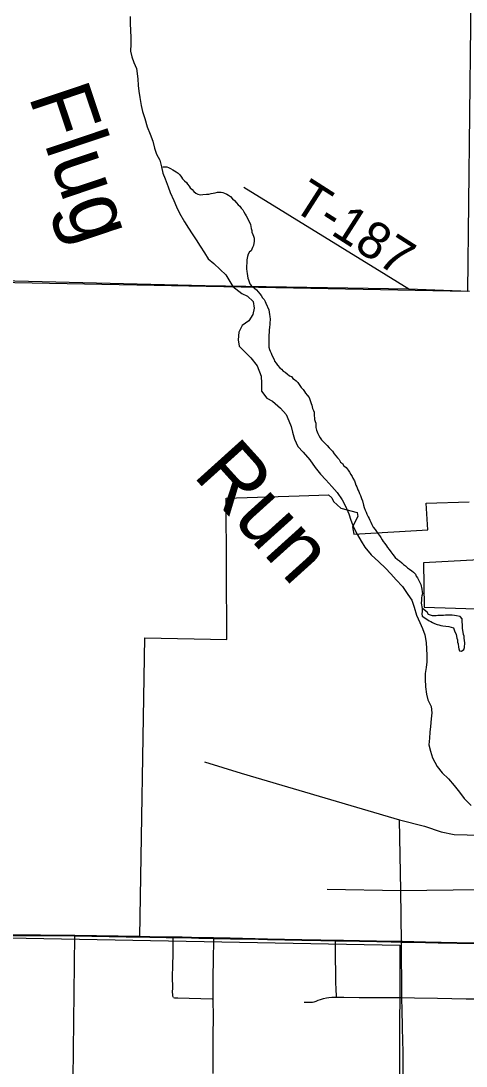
# Model space of a CAD drawing. Extents: x -8.5 to 18.7, y -20.3 to 7.
# Drawn here: x 0.015 to 1.387, y -11.043 to -7.821 of the extents above; entities that cross this region are included whole.
import ezdxf

# ---------------------------------------------------------------- set-up
doc = ezdxf.new("R2010")
doc.units = 0
for name, color, linetype in [('GM_X_City_Street', 7, 'Continuous'), ('GM_X_Corporation', 7, 'Continuous'), ('GM_X_County_Road', 7, 'Continuous'), ('GM_X_Minor_Lake', 7, 'Continuous'), ('GM_X_Minor_River', 7, 'Continuous'), ('GM_X_Minor_River_Text', 7, 'Continuous'), ('GM_X_Section', 7, 'Continuous'), ('GM_X_Township', 7, 'Continuous'), ('GM_X_Township_Road', 7, 'Continuous'), ('GM_X_Township_Road_Text', 7, 'Continuous'), ('SH_Cut_Line', 7, 'Continuous')]:
    doc.layers.add(name, color=color, linetype=linetype)

msp = doc.modelspace()

# ---------------------------------------------------------------- linework, layer by layer
at = {"layer": 'GM_X_City_Street'}
msp.add_line((0.5807, -10.1045), (0.6942, -10.1394), dxfattribs=at)
for points in [[(0.6942, -10.1394), (0.7397, -10.1534), (1.1822, -10.284)], [(1.1822, -10.284), (1.2591, -10.3029), (1.3106, -10.3202), (1.3502, -10.3292), (1.4311, -10.3306)], [(1.1888, -10.6602), (1.1863, -10.501), (1.1822, -10.284)], [(0.9593, -10.4974), (1.1863, -10.501), (1.4281, -10.4988), (1.6026, -10.5019), (1.737, -10.5007)], [(0.4857, -10.8311), (0.4845, -10.8292), (0.4839, -10.8272), (0.4834, -10.8248), (0.4833, -10.8223), (0.4829, -10.8148), (0.4831, -10.8017), (0.4829, -10.7673), (0.4836, -10.7322), (0.4844, -10.6971), (0.4846, -10.6749), (0.4848, -10.6495), (0.4848, -10.6466)], [(0.6078, -11.0651), (0.6078, -11.061), (0.6079, -11.0447), (0.6078, -10.9475), (0.6084, -10.8928), (0.6082, -10.8351), (0.6081, -10.8218), (0.608, -10.767), (0.6084, -10.716), (0.6094, -10.652), (0.6094, -10.6489)], [(0.9884, -10.8303), (0.9878, -10.823), (0.9869, -10.8094), (0.9857, -10.7809), (0.9855, -10.749), (0.9853, -10.7154), (0.9852, -10.6854), (0.985, -10.6603), (0.9849, -10.6564)], [(1.1941, -11.6193), (1.1917, -11.6053), (1.1907, -11.5951), (1.1892, -11.5686), (1.1895, -11.5362), (1.1907, -11.4767), (1.1907, -11.4495), (1.1914, -11.3481), (1.1913, -11.2804), (1.1931, -11.1293), (1.1934, -11.089), (1.1935, -11.0702), (1.1936, -11.0591), (1.1937, -11.0477), (1.1938, -11.0281), (1.1933, -10.9999), (1.1919, -10.9262), (1.19, -10.865), (1.1896, -10.8383), (1.1895, -10.8317), (1.1889, -10.7867), (1.1888, -10.7005), (1.1888, -10.664), (1.1888, -10.6602)], [(0.4857, -10.8311), (0.4885, -10.8321), (0.4911, -10.8325), (0.4947, -10.8326), (0.4989, -10.8325), (0.6042, -10.835), (0.6082, -10.8351)], [(0.8886, -10.8456), (0.906, -10.8459), (0.9137, -10.8452), (0.919, -10.8444), (0.9248, -10.8426), (0.9319, -10.84), (0.9388, -10.8371), (0.9481, -10.8344), (0.957, -10.8326), (0.9641, -10.8315), (0.9738, -10.8307), (0.9834, -10.8304), (0.9884, -10.8303), (1.0107, -10.83), (1.0579, -10.831), (1.0965, -10.8312), (1.1574, -10.8316), (1.1895, -10.8317), (1.2281, -10.8319), (1.299, -10.8334), (1.3878, -10.8352), (1.4261, -10.8355)]]:
    msp.add_lwpolyline(points, dxfattribs=at)
at = {"layer": 'GM_X_Corporation'}
for points in [[(0.1698, -11.612), (0.181, -10.6399), (0.3813, -10.6434), (0.3973, -9.7225), (0.6499, -9.7277), (0.6475, -9.2921), (0.8727, -9.2849), (0.9632, -9.2821), (0.9736, -9.2911), (0.9792, -9.3026), (1.0013, -9.3223), (1.0518, -9.3363), (1.0538, -9.348), (1.0371, -9.3806), (1.0419, -9.4031), (1.2694, -9.3892), (1.2642, -9.3076), (1.3973, -9.3029)], [(1.4272, -9.4823), (1.2561, -9.4913), (1.2586, -9.6281), (1.4512, -9.6345)], [(1.4265, -10.6639), (1.3594, -10.6624), (1.262, -10.6605), (1.1917, -10.6591), (1.1883, -10.6591), (1.1558, -10.6587), (1.1114, -10.6578), (1.0587, -10.6567), (1.01, -10.6558), (0.9885, -10.6554), (0.9845, -10.6553), (0.9393, -10.6545), (0.8811, -10.6531), (0.7751, -10.6511), (0.6606, -10.6488), (0.609, -10.6478), (0.5997, -10.6475), (0.5626, -10.647), (0.5409, -10.6464), (0.5118, -10.6457), (0.4843, -10.6455), (0.4621, -10.6453), (0.4123, -10.644), (0.3813, -10.6434), (0.181, -10.6399), (0.0755, -10.6395), (-0.1044, -10.6386)]]:
    msp.add_lwpolyline(points, dxfattribs=at)
at = {"layer": 'GM_X_County_Road'}
for p, q in [((0.1814, -10.641), (0.3397, -10.6438)), ((0.3397, -10.6438), (0.3817, -10.6445)), ((1.3776, -10.6639), (1.4269, -10.665))]:
    msp.add_line(p, q, dxfattribs=at)
for points in [[(-0.6374, -8.6114), (-0.6211, -8.6091), (-0.5859, -8.6093), (-0.2973, -8.6151), (0.5826, -8.6362), (1.2105, -8.6468), (1.398, -8.6543)], [(-0.729, -10.6299), (-0.6981, -10.6302), (-0.6198, -10.6313), (-0.5055, -10.6329), (-0.4073, -10.6347), (-0.3249, -10.6363), (-0.2072, -10.6385), (-0.104, -10.6397), (0.076, -10.6406), (0.1814, -10.641)], [(0.3817, -10.6445), (0.4127, -10.6451), (0.4626, -10.6464), (0.4848, -10.6466)], [(0.4848, -10.6466), (0.5122, -10.6468), (0.5413, -10.6475), (0.5631, -10.6481), (0.6001, -10.6486), (0.6094, -10.6489)], [(0.6094, -10.6489), (0.6611, -10.6499), (0.7474, -10.6516)], [(0.7474, -10.6516), (0.7756, -10.6522), (0.8816, -10.6542), (0.9398, -10.6556), (0.9849, -10.6564)], [(0.9849, -10.6564), (0.989, -10.6565), (1.0104, -10.6569), (1.0592, -10.6578), (1.1118, -10.6589), (1.1562, -10.6598), (1.1888, -10.6602)], [(1.1888, -10.6602), (1.1922, -10.6602), (1.2624, -10.6616), (1.301, -10.6623)], [(1.301, -10.6623), (1.3598, -10.6635), (1.3776, -10.6639)]]:
    msp.add_lwpolyline(points, dxfattribs=at)
at = {"layer": 'GM_X_Minor_Lake'}
for points in [[(1.2529, -9.6317), (1.2521, -9.6347), (1.2519, -9.6415), (1.251, -9.6483), (1.2524, -9.6552)], [(1.2524, -9.6552), (1.2598, -9.6606), (1.2733, -9.67), (1.2785, -9.6724), (1.2838, -9.6755), (1.2905, -9.6787), (1.298, -9.6811), (1.3033, -9.6827), (1.3101, -9.6844), (1.3161, -9.6853), (1.3252, -9.6862), (1.3342, -9.6879), (1.3418, -9.6896), (1.3486, -9.6912), (1.3507, -9.6974), (1.3528, -9.7042), (1.3572, -9.7111), (1.3578, -9.718), (1.3592, -9.7233), (1.3614, -9.7287), (1.3613, -9.7355), (1.3627, -9.7408), (1.364, -9.7515), (1.3654, -9.7568), (1.3675, -9.7622), (1.3735, -9.7638), (1.3805, -9.7587), (1.3829, -9.7519), (1.3832, -9.7375), (1.3826, -9.7306), (1.3812, -9.7238), (1.3813, -9.7177), (1.3799, -9.7124), (1.3772, -9.6986), (1.3765, -9.6933), (1.3766, -9.688), (1.376, -9.6812), (1.3754, -9.6743), (1.3755, -9.669), (1.3749, -9.6637), (1.369, -9.6568), (1.3584, -9.655), (1.3516, -9.6534), (1.3441, -9.6525), (1.3304, -9.6522), (1.3236, -9.6528), (1.3175, -9.6534), (1.3107, -9.6533), (1.3054, -9.654), (1.3001, -9.6539), (1.2948, -9.6545), (1.2835, -9.6543), (1.2774, -9.6526), (1.2714, -9.6502), (1.267, -9.6433), (1.2529, -9.6317)]]:
    msp.add_lwpolyline(points, dxfattribs=at)
at = {"layer": 'GM_X_Minor_River'}
for points in [[(0.3516, -7.8072), (0.3514, -7.8292), (0.3526, -7.849), (0.3539, -7.8733), (0.3537, -7.8923), (0.3527, -7.9135), (0.357, -7.931), (0.3629, -7.9485), (0.3718, -7.9676), (0.3752, -7.9995), (0.3765, -8.0193), (0.3786, -8.0375), (0.3814, -8.0573), (0.3857, -8.0817), (0.39, -8.0999), (0.3966, -8.1212), (0.4046, -8.1472), (0.4135, -8.17), (0.4216, -8.1914), (0.4274, -8.2127), (0.4333, -8.2317), (0.4437, -8.2501), (0.448, -8.2706), (0.4531, -8.2904), (0.4597, -8.3079), (0.4693, -8.3323), (0.4752, -8.3499), (0.487, -8.3743), (0.4951, -8.3941), (0.504, -8.4132), (0.5197, -8.4399), (0.5316, -8.4591), (0.5435, -8.4766), (0.5554, -8.4958), (0.5681, -8.5149), (0.5808, -8.5355), (0.5919, -8.5546), (0.61, -8.5685), (0.6295, -8.5869), (0.6468, -8.603), (0.6684, -8.639), (0.6962, -8.6613), (0.7135, -8.6691), (0.7308, -8.6859), (0.7343, -8.7065), (0.7303, -8.7254), (0.718, -8.745), (0.6973, -8.76), (0.6865, -8.7804), (0.6847, -8.8039), (0.6875, -8.8237), (0.7048, -8.8398), (0.7235, -8.8597), (0.743, -8.8835), (0.7555, -8.9163), (0.7568, -8.9375), (0.7572, -8.9618), (0.7729, -8.984), (0.7903, -8.9933), (0.8158, -9.0149), (0.833, -9.034), (0.8412, -9.0531), (0.8478, -9.0706), (0.8521, -9.0889), (0.858, -9.1102), (0.8691, -9.1324), (0.8848, -9.15), (0.9058, -9.1737), (0.9222, -9.1975), (0.9387, -9.2181), (0.9552, -9.2358), (0.9731, -9.2557), (0.9904, -9.2749), (1.0053, -9.2971), (1.0157, -9.3169), (1.026, -9.3406), (1.0326, -9.3596), (1.0407, -9.3817), (1.0526, -9.4054), (1.0638, -9.4245), (1.0757, -9.4428), (1.0951, -9.4666), (1.1184, -9.4881), (1.1387, -9.5073), (1.1559, -9.5257)], [(0.4529, -8.2704), (0.465, -8.2707), (0.4703, -8.273), (0.4763, -8.2754), (0.483, -8.2794), (0.4882, -8.2825), (0.4934, -8.2864), (0.4994, -8.2903), (0.5046, -8.295), (0.5098, -8.3019), (0.5135, -8.3073), (0.5194, -8.3135), (0.5253, -8.3189), (0.529, -8.3243), (0.5334, -8.3297), (0.5371, -8.3351), (0.5431, -8.3405), (0.5482, -8.3467), (0.5542, -8.3521), (0.5602, -8.3553), (0.5677, -8.3569), (0.576, -8.3563), (0.5867, -8.355), (0.5942, -8.3544), (0.6018, -8.3531), (0.614, -8.3503), (0.6209, -8.3489), (0.6262, -8.349), (0.6322, -8.3484), (0.6375, -8.3492), (0.6428, -8.3516), (0.6495, -8.3548), (0.6555, -8.3579), (0.6607, -8.3618), (0.6674, -8.3688), (0.6733, -8.3742), (0.68, -8.3819), (0.6852, -8.3874), (0.6904, -8.392), (0.694, -8.3982), (0.6992, -8.4036), (0.7021, -8.4097), (0.7065, -8.4166), (0.7094, -8.422), (0.7204, -8.4427), (0.7225, -8.4488), (0.7239, -8.4542), (0.7253, -8.4602), (0.7267, -8.4671), (0.7273, -8.4724), (0.7302, -8.4793), (0.7316, -8.4847), (0.7338, -8.49), (0.7337, -8.4953), (0.7343, -8.5006), (0.7334, -8.5059), (0.7318, -8.5135), (0.7286, -8.5187), (0.7254, -8.5293), (0.72, -8.533), (0.7153, -8.5397), (0.7137, -8.5465), (0.7119, -8.5571), (0.7117, -8.5685), (0.7108, -8.5745), (0.7106, -8.5851), (0.7119, -8.5928), (0.7126, -8.5996), (0.7139, -8.6065), (0.7145, -8.6133), (0.7167, -8.6186), (0.721, -8.6309), (0.7247, -8.6363), (0.7299, -8.6409), (0.7351, -8.6448), (0.741, -8.6502), (0.7521, -8.6618), (0.7558, -8.6672), (0.7595, -8.6741), (0.7646, -8.6795), (0.7683, -8.6857), (0.7705, -8.691), (0.7791, -8.7117), (0.7819, -8.7254), (0.7825, -8.7323), (0.7831, -8.7399), (0.7828, -8.752), (0.782, -8.7573), (0.7811, -8.7641), (0.7808, -8.7755), (0.7799, -8.7823), (0.7798, -8.7876), (0.7791, -8.8202), (0.7798, -8.8263), (0.7819, -8.8332), (0.7833, -8.8385), (0.7862, -8.8454), (0.7883, -8.8507), (0.7956, -8.8645), (0.797, -8.8699), (0.8015, -8.876)], [(0.8015, -8.876), (0.8066, -8.8822), (0.8133, -8.8899), (0.8185, -8.8946), (0.8237, -8.9), (0.8296, -8.9039), (0.8364, -8.9086), (0.843, -8.9148), (0.849, -8.9172), (0.8535, -8.9226), (0.8587, -8.9257), (0.8639, -8.9304), (0.8691, -8.9358), (0.875, -8.9443), (0.8794, -8.9504), (0.8853, -8.9574), (0.889, -8.9628), (0.8927, -8.9682), (0.8978, -8.9743), (0.9037, -8.9813), (0.9102, -8.9996), (0.9116, -9.0057), (0.9144, -9.0156), (0.9173, -9.0218), (0.9194, -9.0271), (0.9192, -9.0385), (0.9199, -9.0438), (0.9205, -9.0499), (0.9226, -9.0552), (0.9241, -9.0606), (0.9239, -9.0674), (0.9245, -9.0743), (0.9266, -9.0819), (0.9302, -9.0926), (0.9331, -9.0987), (0.9375, -9.1064), (0.9419, -9.1118), (0.9545, -9.1249), (0.9597, -9.1296), (0.9656, -9.1365), (0.9701, -9.1419), (0.976, -9.1474), (0.9804, -9.155), (0.9907, -9.1674), (0.9959, -9.1728), (1.0003, -9.1805), (1.0063, -9.1851), (1.0107, -9.1921), (1.0174, -9.1975), (1.024, -9.206), (1.0284, -9.2121), (1.0321, -9.219), (1.0365, -9.2252), (1.0386, -9.2306), (1.043, -9.239), (1.0451, -9.2451), (1.048, -9.252), (1.0502, -9.2573), (1.0538, -9.2658), (1.0567, -9.2719), (1.0589, -9.2772), (1.0618, -9.2834), (1.0653, -9.2926), (1.0682, -9.3002), (1.071, -9.3139), (1.0731, -9.3208), (1.0759, -9.3292), (1.0796, -9.3353), (1.0818, -9.3414), (1.0854, -9.3491), (1.0883, -9.3545), (1.0912, -9.3598), (1.0934, -9.3659), (1.097, -9.3736), (1.1014, -9.3813), (1.1073, -9.389), (1.1117, -9.3944), (1.1153, -9.4005), (1.1205, -9.4067), (1.1242, -9.4136), (1.1286, -9.4205), (1.1315, -9.4259), (1.1366, -9.4321), (1.1426, -9.439), (1.1455, -9.4444), (1.1507, -9.4506), (1.1558, -9.4575), (1.1617, -9.466), (1.1691, -9.4744), (1.1765, -9.4807), (1.1825, -9.4853), (1.1892, -9.4908), (1.1944, -9.4962), (1.2003, -9.5009), (1.207, -9.5071), (1.213, -9.511), (1.2197, -9.5157), (1.2257, -9.5196), (1.2316, -9.5265), (1.2338, -9.5319), (1.2374, -9.5373)], [(1.1559, -9.5257), (1.1724, -9.5441), (1.1911, -9.5641), (1.2083, -9.5885), (1.2202, -9.6069), (1.2276, -9.6282), (1.2349, -9.6526), (1.2445, -9.6755), (1.2526, -9.6938), (1.26, -9.7136), (1.2643, -9.7364), (1.2669, -9.7759), (1.2666, -9.7964), (1.2649, -9.8139), (1.2617, -9.8328), (1.2615, -9.8503), (1.2627, -9.8738), (1.2655, -9.8959), (1.2699, -9.9134), (1.2795, -9.934), (1.2815, -9.9538), (1.2798, -9.972), (1.278, -9.9955), (1.2756, -10.0129), (1.2746, -10.0319), (1.2728, -10.0524), (1.2779, -10.0722), (1.2838, -10.0927), (1.2986, -10.1195), (1.3136, -10.1386), (1.3331, -10.157), (1.3511, -10.1777), (1.3668, -10.1984), (1.3817, -10.2175), (1.4035, -10.239)], [(1.2374, -9.5373), (1.2411, -9.5442), (1.244, -9.5495), (1.2476, -9.558), (1.2511, -9.5724), (1.2524, -9.5808), (1.2531, -9.5861), (1.2514, -9.5929), (1.2505, -9.599), (1.2504, -9.6066), (1.2494, -9.6157), (1.2523, -9.6316)]]:
    msp.add_lwpolyline(points, dxfattribs=at)
at = {"layer": 'GM_X_Section'}
for points in [[(1.4135, -6.7407), (1.3918, -8.6545), (-0.6492, -8.616), (-0.5532, -6.824), (-0.5496, -6.7247)], [(-0.7383, -10.6339), (1.1828, -10.6703), (1.1777, -12.6489), (-0.8294, -12.6494)]]:
    msp.add_lwpolyline(points, close=True, dxfattribs=at)
at = {"layer": 'GM_X_Township'}
msp.add_lwpolyline([(1.4265, -10.6639), (1.3594, -10.6624), (1.262, -10.6605), (1.1917, -10.6591), (1.1883, -10.6591), (1.1558, -10.6587), (1.1114, -10.6578), (1.0587, -10.6567), (1.01, -10.6558), (0.9885, -10.6554), (0.9845, -10.6553), (0.9393, -10.6545), (0.8811, -10.6531), (0.7751, -10.6511), (0.6606, -10.6488), (0.609, -10.6478), (0.5997, -10.6475), (0.5626, -10.647), (0.5409, -10.6464), (0.5118, -10.6457), (0.4843, -10.6455), (0.4621, -10.6453), (0.4123, -10.644), (0.3813, -10.6434), (0.181, -10.6399), (0.0755, -10.6395), (-0.1044, -10.6386)], dxfattribs=at)
at = {"layer": 'GM_X_Township_Road'}
msp.add_lwpolyline([(0.7023, -8.3335), (1.1408, -8.6033), (1.2105, -8.6468)], dxfattribs=at)
at = {"layer": 'SH_Cut_Line'}
for points in [[(1.4265, -10.6639), (1.3594, -10.6624), (1.262, -10.6605), (1.1917, -10.6591), (1.1883, -10.6591), (1.1558, -10.6587), (1.1114, -10.6578), (1.0587, -10.6567), (1.01, -10.6558), (0.9885, -10.6554), (0.9845, -10.6553), (0.9393, -10.6545), (0.8811, -10.6531), (0.7751, -10.6511), (0.6606, -10.6488), (0.609, -10.6478), (0.5997, -10.6475), (0.5626, -10.647), (0.5409, -10.6464), (0.5118, -10.6457), (0.4843, -10.6455), (0.4621, -10.6453), (0.4123, -10.644), (0.3813, -10.6434), (0.181, -10.6399), (0.0755, -10.6395), (-0.1044, -10.6386)], [(-0.1044, -10.6386), (0.0755, -10.6395), (0.181, -10.6399), (0.3813, -10.6434), (0.4123, -10.644), (0.4621, -10.6453), (0.4843, -10.6455), (0.5118, -10.6457), (0.5409, -10.6464), (0.5626, -10.647), (0.5997, -10.6475), (0.609, -10.6478), (0.6606, -10.6488), (0.7751, -10.6511), (0.8811, -10.6531), (0.9393, -10.6545), (0.9845, -10.6553), (0.9885, -10.6554), (1.01, -10.6558), (1.0587, -10.6567), (1.1114, -10.6578), (1.1558, -10.6587), (1.1883, -10.6591), (1.1917, -10.6591), (1.262, -10.6605), (1.3594, -10.6624), (1.4265, -10.6639)]]:
    msp.add_lwpolyline(points, dxfattribs=at)

# ---------------------------------------------------------------- texts
at = {"layer": 'GM_X_Minor_River_Text'}
for s, height, rotation, p in [('Flug', 0.18952, 288.5487, (0.0379, -8.0522)), ('Run', 0.18951, 312.0477, (0.5426, -9.2222))]:
    msp.add_text(s, height=height, rotation=rotation, dxfattribs=at).set_placement(p)
at = {"layer": 'GM_X_Township_Road_Text'}
msp.add_text('T-187', height=0.11364, rotation=327.3955, dxfattribs=at).set_placement((0.8461, -8.3992))

doc.saveas('drawing.dxf')
